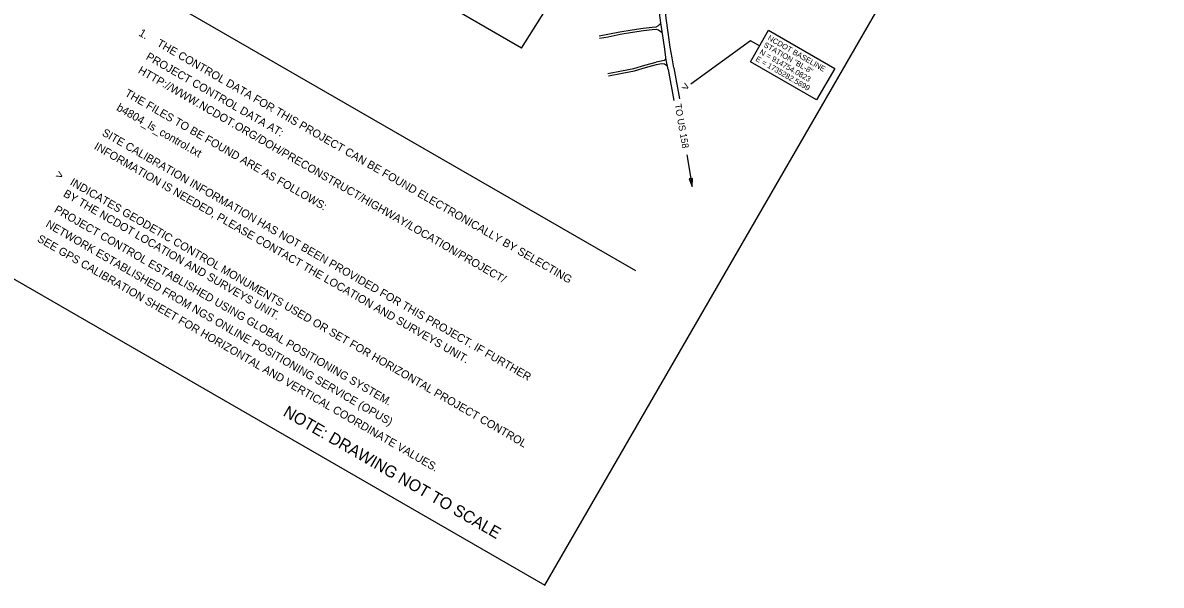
# Model space of a CAD drawing. Extents: x 1729269 to 1736953, y 913137 to 919486.
# Drawn here: x 1733139 to 1736849, y 913137 to 914972 of the extents above; entities that cross this region are included whole.
import ezdxf

# ---------------------------------------------------------------- set-up
doc = ezdxf.new("R2010")
doc.units = 0
for name, color, linetype in [('CTL Sheet Border CELL', 7, 'Continuous'), ('CTL Sheet Notes CELL', 7, 'Continuous'), ('CTL Sheet Text', 7, 'Continuous'), ('Default', 7, 'Continuous'), ('Exist Roads EOP', 7, 'Continuous'), ('Exist Roads Soil', 7, 'Continuous'), ('Old_Level_57', 7, 'Continuous'), ('Proposed Right of Way Monument PSD Text', 7, 'Continuous'), ('Sheet Data Field CELL', 7, 'Continuous')]:
    doc.layers.add(name, color=color, linetype=linetype)

msp = doc.modelspace()

# ---------------------------------------------------------------- linework, layer by layer
at = {"layer": 'CTL Sheet Border CELL'}
msp.add_lwpolyline([(1736848.9, 916616.2), (1731878.6, 919485.8), (1729869.9, 916006.6), (1734840.2, 913137)], close=True, dxfattribs=at)
at = {"layer": 'CTL Sheet Notes CELL'}
msp.add_line((1733546.9, 915080.5), (1735135.7, 914163.2), dxfattribs=at)
at = {"layer": 'CTL Sheet Text'}
for p, q in [((1734764.2, 914889.5), (1733866.3, 915408)), ((1734764.2, 914889.5), (1735086.8, 915399.5)), ((1735302.6, 914540.6), (1735320.6, 914437.2))]:
    msp.add_line(p, q, dxfattribs=at)
msp.add_lwpolyline([(1735321.8, 914464.3), (1735310.2, 914462.3), (1735320.6, 914437.2)], close=True, dxfattribs=at)
at = {"layer": 'Default'}
msp.add_lwpolyline([(1735569.5, 914947.6), (1735785.1, 914823.1), (1735725.7, 914720.3), (1735510.1, 914844.8)], close=True, dxfattribs=at)
msp.add_lwpolyline([(1735539.8, 914896.2), (1735510.4, 914913.2), (1735316.2, 914771.7)], dxfattribs=at)
at = {"layer": 'Exist Roads EOP'}
for p, q in [((1735242.5, 914819.2), (1735261, 914718)), ((1735260.6, 914824.7), (1735279.2, 914723.2))]:
    msp.add_line(p, q, dxfattribs=at)
for points in [[(1735242.5, 914819.2), (1735236, 914850.6), (1735229.7, 914892.9), (1735224.3, 914929.5), (1735218.2, 914971.6), (1735214, 915003.7), (1735208.6, 915044.9), (1735202.9, 915083.8), (1735195.5, 915123.4), (1735187.7, 915160.5), (1735177.1, 915196.8), (1735165.8, 915229.4), (1735153.3, 915259.8), (1735135.8, 915296.9), (1735118.8, 915329.6), (1735099.9, 915362.6), (1735080.5, 915391.6), (1735075.9, 915397.9)], [(1735260.6, 914824.7), (1735254.7, 914857), (1735249.1, 914892.7), (1735242.4, 914939.7), (1735236, 914986.4), (1735230.7, 915026.7), (1735221.6, 915087.2), (1735215.3, 915122.6), (1735207.4, 915156.6), (1735198.8, 915189.4), (1735190.1, 915217.8)]]:
    msp.add_lwpolyline(points, dxfattribs=at)
at = {"layer": 'Exist Roads Soil'}
for points in [[(1735016.9, 914929), (1735045.1, 914934.1), (1735084.1, 914941.8), (1735124.2, 914949.3), (1735160.4, 914954.5), (1735189.7, 914957.9), (1735202.9, 914958.3)], [(1735018.3, 914921.3), (1735046.5, 914926.4), (1735085.6, 914934.1), (1735125.5, 914941.6), (1735161.4, 914946.8), (1735190.2, 914950.1), (1735203.1, 914950.5)], [(1735202.9, 914958.3), (1735210.3, 914962.5), (1735218.4, 914970.4)], [(1735203.1, 914950.5), (1735210.3, 914948.8), (1735222.7, 914940.3)], [(1735045.6, 914806.1), (1735090.5, 914814.5), (1735130.7, 914823), (1735166.2, 914833.6), (1735202.5, 914842.9)], [(1735047.1, 914798.4), (1735092, 914806.9), (1735132.6, 914815.5), (1735168.3, 914826.1), (1735204.4, 914835.4)], [(1735235.4, 914855.1), (1735229, 914849), (1735213.6, 914845.4), (1735202.5, 914842.9)], [(1735204.4, 914835.4), (1735219.9, 914838.5), (1735229.9, 914837.7), (1735240.1, 914830.8)]]:
    msp.add_lwpolyline(points, dxfattribs=at)

# ---------------------------------------------------------------- texts
at = {"layer": 'CTL Sheet Notes CELL'}
for s, rotation, p in [('1.    THE CONTROL DATA FOR THIS PROJECT CAN BE FOUND ELECTRONICALLY BY SELECTING', 330, (1733514.4, 914931.5)), ('PROJECT CONTROL DATA AT:', 330, (1733538, 914854.2)), ('HTTP://WWW.NCDOT.ORG/DOH/PRECONSTRUCT/HIGHWAY/LOCATION/PROJECT/', 330, (1733512.2, 914809.4)), ('THE FILES TO BE FOUND ARE AS FOLLOWS:', 330, (1733469.1, 914734.7)), ('b4804_ls_control.txt', 330, (1733442, 914687.8)), ('SITE CALIBRATION INFORMATION HAS NOT BEEN PROVIDED FOR THIS PROJECT. IF FURTHER', 330, (1733394.6, 914605.8)), ('INFORMATION IS NEEDED, PLEASE CONTACT THE LOCATION AND SURVEYS UNIT.', 330, (1733368.9, 914561.3)), ('INDICATES GEODETIC CONTROL MONUMENTS USED OR SET FOR HORIZONTAL PROJECT CONTROL', 329.8948, (1733290.4, 914444.6)), ('BY THE NCDOT LOCATION AND SURVEYS UNIT.', 329.8948, (1733268.5, 914407.1)), ('PROJECT CONTROL ESTABLISHED USING GLOBAL POSITIONING SYSTEM.', 329.8948, (1733238.9, 914355.7)), ('NETWORK ESTABLISHED FROM NGS ONLINE POSITIONING SERVICE (OPUS)', 329.8948, (1733211.3, 914307.9)), ('SEE GPS CALIBRATION SHEET FOR HORIZONTAL AND VERTICAL COORDINATE VALUES.', 329.8948, (1733183.6, 914260))]:
    msp.add_text(s, height=26.087, rotation=rotation, dxfattribs=at).set_placement(p)
at = {"layer": 'CTL Sheet Text'}
msp.add_text('TO US 158', height=22, rotation=279.8791, dxfattribs=at).set_placement((1735263.1, 914705.7))
at = {"layer": 'Old_Level_57'}
for p in [(1735282.4, 914757.2), (1733242.4, 914468.8)]:
    msp.add_text('>', height=28.7, rotation=330.0142, dxfattribs=at).set_placement(p)
at = {"layer": 'Proposed Right of Way Monument PSD Text'}
for s, p in [('STATION "BL-8"', (1735551.5, 914894.5)), ('NCDOT BASELINE', (1735564.7, 914917.4)), ('N = 914754.0823', (1735538.3, 914871.6)), ('E = 1735282.5899', (1735525.1, 914848.8))]:
    msp.add_text(s, height=17.6, rotation=330, dxfattribs=at).set_placement(p)
at = {"layer": 'Sheet Data Field CELL'}
msp.add_text('NOTE: DRAWING NOT TO SCALE', height=38.261, rotation=329.8948, dxfattribs=at).set_placement((1733984.3, 913691.8))

doc.saveas('drawing.dxf')
